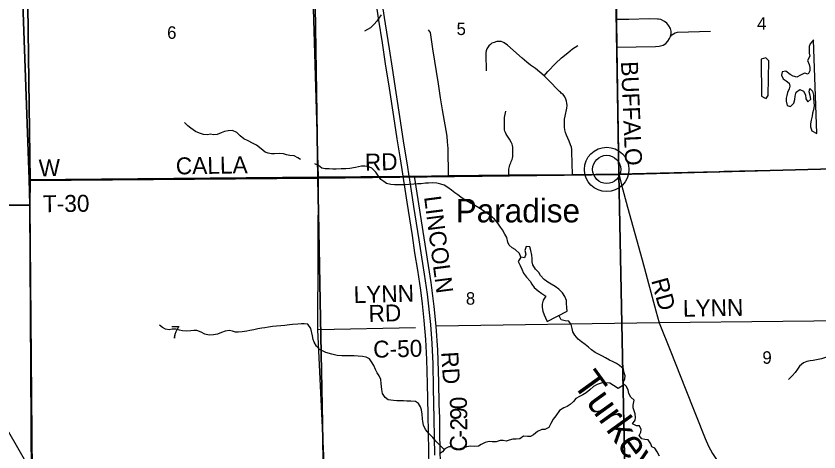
# Model space of a CAD drawing. Extents: x 0 to 36.9, y 0 to 22.
# Drawn here: x 4.166 to 6.858, y 18.601 to 20.063 of the extents above; entities that cross this region are included whole.
import ezdxf

# ---------------------------------------------------------------- set-up
doc = ezdxf.new("R2010")
doc.units = 0
for name, color, linetype in [('GM_X_County_Road', 7, 'Continuous'), ('GM_X_County_Road_Text', 7, 'Continuous'), ('GM_X_Minor_Lake', 7, 'Continuous'), ('GM_X_Minor_River', 7, 'Continuous'), ('GM_X_Minor_River_Text', 7, 'Continuous'), ('GM_X_Rail_Line', 7, 'Continuous'), ('GM_X_Section', 7, 'Continuous'), ('GM_X_Section_Text', 7, 'Continuous'), ('GM_X_State_Route', 7, 'Continuous'), ('GM_X_Township_Road', 7, 'Continuous'), ('GM_X_Township_Road_Text', 7, 'Continuous'), ('GM_X_Unincorporated', 7, 'Continuous'), ('GM_X_Unincorporated_Location', 7, 'Continuous'), ('GM_X_Unincorporated_Text', 7, 'Continuous')]:
    doc.layers.add(name, color=color, linetype=linetype)

msp = doc.modelspace()

# ---------------------------------------------------------------- linework, layer by layer
at = {"layer": 'GM_X_County_Road'}
for p, q in [((5.1803, 19.5234), (5.1498, 20.5289)), ((4.2126, 19.4308), (4.2097, 19.515)), ((5.5055, 19.0174), (5.1771, 19.01))]:
    msp.add_line(p, q, dxfattribs=at)
for points in [[(6.1729, 20.5473), (6.1788, 20.0773), (6.1787, 20.0516), (6.1801, 19.9585), (6.187, 19.5342)], [(5.0673, 17.4931), (5.0594, 17.9986), (5.0622, 18.0085), (5.0708, 18.0163), (5.188, 18.0224), (5.1928, 18.0266), (5.1952, 18.0408), (5.2008, 18.5186), (5.1771, 19.01), (5.1803, 19.5234)], [(5.6045, 18.5243), (5.5945, 18.533), (5.5895, 18.5452), (5.5877, 18.5992), (5.5866, 18.6737), (5.5863, 18.715), (5.5843, 18.7612), (5.5835, 18.8365), (5.5797, 18.9426), (5.5744, 19.0226), (5.5675, 19.0889), (5.5575, 19.1695), (5.5019, 19.5264)], [(6.187, 19.5342), (6.1956, 19.4972), (6.2161, 19.4219), (6.2648, 19.2449), (6.3107, 19.0737), (6.3225, 19.0341)], [(3.21, 19.4177), (3.802, 19.4268), (4.2126, 19.4308)], [(7.1513, 19.0425), (6.3225, 19.0341), (5.5744, 19.0226)], [(6.3225, 19.0341), (6.3608, 18.9363), (6.4096, 18.8146), (6.4758, 18.6464), (6.4875, 18.6201), (6.5008, 18.5958), (6.5286, 18.5528), (6.5955, 18.45), (6.6081, 18.4277), (6.6215, 18.3998), (6.6322, 18.3709), (6.638, 18.3599), (6.6455, 18.3515), (6.6522, 18.3445)]]:
    msp.add_lwpolyline(points, dxfattribs=at)
at = {"layer": 'GM_X_Minor_Lake'}
for points in [[(6.8392, 19.983), (6.8279, 19.9705), (6.8254, 19.961), (6.8252, 19.9485), (6.8254, 19.939), (6.8267, 19.9284), (6.819, 19.9138), (6.8249, 19.901), (6.8277, 19.8908), (6.8271, 19.8794), (6.8216, 19.8679), (6.809, 19.8719), (6.7962, 19.8648), (6.7833, 19.8585), (6.7711, 19.8613), (6.7612, 19.8673), (6.7465, 19.8784), (6.734, 19.8767), (6.7319, 19.8645), (6.7378, 19.8524), (6.7474, 19.8465), (6.7574, 19.8383), (6.7603, 19.8281), (6.7578, 19.8186), (6.7519, 19.8067), (6.7501, 19.7972), (6.7484, 19.7877), (6.7481, 19.7782), (6.7507, 19.763), (6.7625, 19.7598), (6.7734, 19.7706), (6.777, 19.7836), (6.7783, 19.795), (6.7815, 19.8076), (6.7935, 19.8169), (6.8065, 19.8118), (6.8128, 19.7986), (6.8138, 19.7861), (6.82, 19.776), (6.8309, 19.7845), (6.8281, 19.7962), (6.8245, 19.8087), (6.8277, 19.8205), (6.8362, 19.8108), (6.8391, 19.7976), (6.84, 19.7881), (6.8406, 19.7737), (6.8412, 19.763), (6.8399, 19.7486), (6.8366, 19.7371), (6.8345, 19.7272), (6.8313, 19.7139), (6.8296, 19.7021), (6.829, 19.6918), (6.8334, 19.6782), (6.8506, 19.6689)], [(6.8506, 19.6689), (6.8392, 19.983)], [(6.6897, 19.9131), (6.68, 19.9232), (6.6637, 19.9188), (6.6657, 19.7947), (6.675, 19.7884), (6.6807, 19.7869), (6.6874, 19.7965)], [(6.6874, 19.7965), (6.6897, 19.9131)], [(6.0131, 19.0734), (6.0129, 19.0852), (6.0119, 19.0992), (6.011, 19.1087), (6.0062, 19.1223), (5.9984, 19.1343), (5.9853, 19.1474), (5.9734, 19.1555), (5.9595, 19.1637), (5.9484, 19.1707), (5.9365, 19.1792), (5.9241, 19.1931), (5.919, 19.2032), (5.9074, 19.2144), (5.8988, 19.2291), (5.8963, 19.2389), (5.8962, 19.2499), (5.8952, 19.2613), (5.8923, 19.2765), (5.8883, 19.2889), (5.8758, 19.2899), (5.8714, 19.2765), (5.8746, 19.264), (5.8706, 19.2526), (5.8585, 19.2539), (5.8496, 19.2397), (5.8559, 19.2265), (5.8618, 19.2141), (5.8677, 19.2005), (5.877, 19.187), (5.8894, 19.1743), (5.8957, 19.1634), (5.9034, 19.1529), (5.9162, 19.1409), (5.9292, 19.1324), (5.9416, 19.1231), (5.933, 19.1101), (5.9294, 19.0963), (5.9296, 19.0857), (5.9321, 19.0732), (5.9369, 19.0604), (5.9412, 19.0506), (5.9471, 19.0389)], [(5.9471, 19.0389), (6.0131, 19.0734)]]:
    msp.add_lwpolyline(points, dxfattribs=at)
at = {"layer": 'GM_X_Minor_River'}
for points in [[(5.3902, 20.0674), (5.382, 20.0566), (5.375, 20.0462), (5.3665, 20.0358), (5.3538, 20.0238), (5.344, 20.0179), (5.3338, 20.0125)], [(5.1198, 19.5816), (5.1102, 19.5879), (5.0983, 19.5941), (5.0834, 19.5958), (5.0731, 19.5982), (5.0621, 19.6011), (5.048, 19.6024), (5.0328, 19.6009), (5.0226, 19.6008), (5.0112, 19.6028), (5.0016, 19.6068), (4.9877, 19.618), (4.9723, 19.6299), (4.9582, 19.6364), (4.9436, 19.6445), (4.9294, 19.6511), (4.9175, 19.6619), (4.9059, 19.6723), (4.8921, 19.6789), (4.8769, 19.6783), (4.8652, 19.6765), (4.8539, 19.6718), (4.8403, 19.6662), (4.8274, 19.6652), (4.8179, 19.6666), (4.8077, 19.6653), (4.794, 19.6662), (4.7814, 19.6701), (4.768, 19.6763), (4.7518, 19.6867), (4.7418, 19.6945), (4.7306, 19.7057)], [(5.8585, 19.2539), (5.8537, 19.2663), (5.8394, 19.2797), (5.8287, 19.2852), (5.8186, 19.2949), (5.8143, 19.3051), (5.811, 19.3206), (5.8051, 19.3315), (5.7972, 19.3458), (5.7902, 19.3555), (5.7816, 19.3679), (5.7704, 19.3817), (5.7546, 19.3955), (5.743, 19.4025), (5.7304, 19.4114), (5.7169, 19.4199), (5.7039, 19.4276), (5.692, 19.4346), (5.6789, 19.4416), (5.6678, 19.4482), (5.6567, 19.456), (5.647, 19.4631), (5.6374, 19.4705), (5.6259, 19.479), (5.6139, 19.4879), (5.6009, 19.4956), (5.5906, 19.4996), (5.5765, 19.5028), (5.5628, 19.5041), (5.5487, 19.5031), (5.5385, 19.5021), (5.5245, 19.5007), (5.512, 19.5001), (5.4991, 19.4991), (5.4831, 19.4981), (5.4721, 19.4975), (5.4596, 19.4969), (5.4478, 19.4971), (5.4342, 19.4972), (5.4227, 19.4985), (5.4083, 19.5017), (5.3986, 19.5084), (5.389, 19.5146), (5.3785, 19.5289), (5.3719, 19.539), (5.3587, 19.5532), (5.3457, 19.5587), (5.3355, 19.5596), (5.3245, 19.5591), (5.304, 19.5553), (5.2847, 19.5519), (5.2714, 19.5509), (5.2555, 19.5502), (5.2388, 19.5499), (5.2278, 19.5501), (5.216, 19.5503), (5.202, 19.5512), (5.1913, 19.5529), (5.1801, 19.5622), (5.1679, 19.5677)], [(6.3234, 18.5862), (6.3152, 18.6008), (6.3074, 18.6136), (6.2978, 18.6176), (6.2938, 18.6285), (6.2856, 18.6413), (6.2738, 18.643), (6.2635, 18.6451), (6.2553, 18.6563), (6.2601, 18.6666), (6.2618, 18.6765), (6.2563, 18.6886), (6.2464, 18.688), (6.2326, 18.6954), (6.2419, 18.7073), (6.2432, 18.7168), (6.2411, 18.7285), (6.2383, 18.7387), (6.2347, 18.7485), (6.2349, 18.758), (6.238, 18.7744), (6.2272, 18.7848), (6.2202, 18.7973), (6.218, 18.8097), (6.2117, 18.8218), (6.2006, 18.8318), (6.2075, 18.846), (6.2081, 18.8566), (6.2041, 18.8691), (6.2024, 18.8793), (6.1896, 18.8908), (6.1785, 18.8975), (6.1651, 18.9037), (6.1555, 18.9084), (6.1425, 18.9162), (6.1317, 18.9217), (6.1206, 18.9272), (6.108, 18.9349), (6.0956, 18.9438), (6.0852, 18.9524), (6.0737, 18.9613), (6.0614, 18.9698), (6.0506, 18.9791), (6.0397, 18.9922), (6.0323, 19.0042), (6.0302, 19.0151), (6.0266, 19.028), (6.0191, 19.04), (6.007, 19.0402), (5.9936, 19.0445), (5.9862, 19.0594)], [(5.6013, 18.6089), (5.5737, 18.6369), (5.5632, 18.6492), (5.5505, 18.6615), (5.5384, 18.6761), (5.5317, 18.6904), (5.5296, 18.7026), (5.5287, 18.7124), (5.5273, 18.7276), (5.5251, 18.7416), (5.5223, 18.7518), (5.5152, 18.7634), (5.5056, 18.7697), (5.49, 18.7709), (5.476, 18.7714), (5.4646, 18.772), (5.4528, 18.7718), (5.4422, 18.772), (5.4308, 18.7733), (5.414, 18.7757), (5.4032, 18.7831), (5.395, 18.797), (5.3925, 18.8106), (5.3902, 18.8299), (5.3885, 18.8439), (5.3833, 18.856), (5.3763, 18.8661), (5.3712, 18.8778), (5.3656, 18.8906), (5.3578, 18.903), (5.3508, 18.9135), (5.3397, 18.9186), (5.3271, 18.9214), (5.3134, 18.9223), (5.299, 18.9228), (5.2823, 18.9232), (5.2697, 18.923), (5.2583, 18.9232), (5.2424, 18.9248), (5.2248, 18.9283), (5.2046, 18.934), (5.195, 18.9384), (5.1835, 18.9446), (5.1727, 18.9562), (5.1653, 18.9686), (5.162, 18.9784), (5.1596, 18.9902), (5.1546, 19.0151), (5.144, 19.0297), (5.1322, 19.031), (5.1224, 19.0305), (5.1102, 19.0295), (5.0928, 19.0284), (5.0826, 19.0275), (5.0667, 19.0253), (5.0541, 19.024), (5.039, 19.0226), (5.0253, 19.0212), (5.0121, 19.0194), (5, 19.0173), (4.9901, 19.0164), (4.9765, 19.0139), (4.9632, 19.011), (4.9493, 19.0081), (4.9394, 19.006), (4.9235, 19.0038), (4.9106, 19.0028), (4.9011, 19.003), (4.8916, 19.0055), (4.8813, 19.0084), (4.8669, 19.0062), (4.8544, 19.0018), (4.8413, 18.9955), (4.828, 18.9938), (4.8128, 18.9931), (4.7991, 18.9959), (4.7861, 19.0029), (4.7715, 19.0083), (4.7617, 19.0081), (4.7518, 19.0076), (4.7382, 19.0058), (4.7237, 19.0075), (4.7134, 19.0099), (4.702, 19.0124), (4.6894, 19.0125), (4.6796, 19.0109), (4.667, 19.0125), (4.6574, 19.0184), (4.6471, 19.0262)], [(6.9595, 18.9484), (6.9352, 18.9495), (6.9246, 18.947), (6.9137, 18.94), (6.9028, 18.9303), (6.8923, 18.9236), (6.8795, 18.9181), (6.8663, 18.9137), (6.8493, 18.9099), (6.8387, 18.9079), (6.8285, 18.9061), (6.8171, 18.904), (6.8062, 18.9), (6.7931, 18.8888), (6.7857, 18.8788), (6.7783, 18.8677), (6.7682, 18.8561), (6.7555, 18.8441)], [(6.206, 18.827), (6.1842, 18.8133), (6.1688, 18.824), (6.1569, 18.8318), (6.1383, 18.833), (6.1276, 18.8317), (6.1144, 18.8269), (6.1024, 18.8206), (6.0901, 18.8097), (6.077, 18.7992), (6.0664, 18.7926), (6.0555, 18.7867), (6.0428, 18.7796), (6.035, 18.7696), (6.0237, 18.7596), (6.0136, 18.7533), (6.0027, 18.7486), (5.9876, 18.7399), (5.9758, 18.7219), (5.9662, 18.7103), (5.9588, 18.6962), (5.9518, 18.6827), (5.9387, 18.6757), (5.9292, 18.6755), (5.9137, 18.6688), (5.9006, 18.6583), (5.8905, 18.6528), (5.8802, 18.6522), (5.8673, 18.6535), (5.8549, 18.645), (5.8428, 18.644), (5.8314, 18.6434), (5.8189, 18.6398), (5.8087, 18.6369), (5.7985, 18.6386), (5.789, 18.6388), (5.7757, 18.6344), (5.7625, 18.6346), (5.7522, 18.6355), (5.7386, 18.6319), (5.7258, 18.6256), (5.716, 18.6205), (5.7016, 18.6191), (5.6898, 18.62), (5.6758, 18.6175), (5.6622, 18.6119), (5.6478, 18.6101), (5.636, 18.6137), (5.6264, 18.6177), (5.6166, 18.6179), (5.6034, 18.6116), (5.5956, 18.6016), (5.5855, 18.5942)]]:
    msp.add_lwpolyline(points, dxfattribs=at)
at = {"layer": 'GM_X_Rail_Line'}
for points in [[(8.9, 14.5158), (8.9, 20.5927), (8.7004, 20.5894), (8.4791, 20.5781), (8.4706, 20.5777), (8.1451, 20.581), (7.7514, 20.5725), (7.4889, 20.5693), (7.1656, 20.5637), (7.1468, 20.5633), (6.1727, 20.5478), (5.9236, 20.5446), (5.3186, 20.5329), (5.2978, 20.5324), (5.1496, 20.5295), (4.5929, 20.5183), (4.1742, 20.5119), (4.2095, 19.5156), (4.2124, 19.4314), (4.22, 18.531), (4.2174, 18.4382), (4.2214, 17.442), (4.2237, 16.806), (4.2428, 16.065)], [(4.2428, 16.065), (4.2237, 16.806), (4.2214, 17.442), (4.2174, 18.4382), (4.22, 18.531), (4.2124, 19.4314), (4.2095, 19.5156), (4.1742, 20.5119), (3.4355, 20.4995), (3.1942, 20.4953), (2.6054, 20.4898), (2.1, 20.4802), (2.1, 14.4405)]]:
    msp.add_lwpolyline(points, dxfattribs=at)
at = {"layer": 'GM_X_Section'}
for points in [[(7.1483, 20.5676), (7.1591, 19.5574), (6.1867, 19.5319), (6.1696, 20.5537), (6.9427, 20.5639)], [(6.1696, 20.5537), (6.1867, 19.5319), (5.1777, 19.5195), (5.1623, 20.5304), (5.285, 20.533), (5.9343, 20.5451)], [(4.1996, 20.5167), (4.2133, 19.5112), (4.212, 19.4289), (3.2188, 19.419), (3.2025, 20.497), (3.3829, 20.4998), (3.9553, 20.5131)], [(5.1623, 20.5304), (5.1777, 19.5195), (4.2133, 19.5112), (4.1996, 20.5167), (4.6217, 20.5229)], [(7.1591, 19.5574), (7.173, 18.5435), (6.2072, 18.5313), (6.1867, 19.5319)], [(5.1777, 19.5195), (5.197, 18.519), (4.2176, 18.508), (4.212, 19.4289), (4.2133, 19.5112)], [(6.1867, 19.5319), (6.2072, 18.5313), (5.197, 18.519), (5.1777, 19.5195)], [(4.212, 19.4289), (4.2176, 18.508), (4.219, 18.4391), (3.226, 18.4277), (3.2188, 19.419)]]:
    msp.add_lwpolyline(points, close=True, dxfattribs=at)
at = {"layer": 'GM_X_State_Route'}
for points in [[(5.5518, 18.5008), (5.5494, 18.6039), (5.5482, 18.6658), (5.5474, 18.7263), (5.5452, 18.8301), (5.5436, 18.9104), (5.5401, 18.9785), (5.5346, 19.0413), (5.5284, 19.0973), (5.5226, 19.1436), (5.5124, 19.2106), (5.5034, 19.2688), (5.4945, 19.3274), (5.477, 19.4386), (5.4636, 19.5258), (5.4624, 19.5335), (5.4547, 19.5847), (5.444, 19.6519), (5.4325, 19.7268), (5.4178, 19.8212), (5.4047, 19.9033), (5.394, 19.9735), (5.3823, 20.049), (5.3732, 20.1089)], [(5.5698, 18.5896), (5.5687, 18.6515), (5.5678, 18.712), (5.5657, 18.8158), (5.5641, 18.8961), (5.5606, 18.9642), (5.5563, 19.0287), (5.5448, 19.13), (5.5348, 19.1971), (5.5262, 19.2539), (5.5173, 19.3126), (5.4996, 19.4244), (5.4848, 19.5215), (5.484, 19.5261), (5.478, 19.5644), (5.4665, 19.6373), (5.4552, 19.712), (5.4402, 19.8071), (5.4279, 19.8887), (5.4177, 19.9538), (5.4047, 20.0375), (5.3958, 20.0944)], [(4.2202, 18.5304), (4.0532, 18.8191), (4.0295, 18.8744), (3.802, 19.4268)]]:
    msp.add_lwpolyline(points, dxfattribs=at)
at = {"layer": 'GM_X_Township_Road'}
msp.add_line((4.2097, 19.515), (5.1803, 19.5234), dxfattribs=at)
for points in [[(6.3193, 20.0527), (6.3163, 20.0531), (6.2881, 20.0539), (6.2199, 20.0518), (6.1787, 20.0516)], [(6.36, 19.9948), (6.3621, 20.0045), (6.3618, 20.0123), (6.3601, 20.0216), (6.3549, 20.0307), (6.348, 20.0395), (6.3404, 20.0453), (6.3274, 20.0516), (6.3193, 20.0527)], [(5.6156, 19.5281), (5.6141, 19.6192), (5.6127, 19.6413), (5.6108, 19.6606), (5.5955, 19.7488), (5.5893, 19.7892), (5.5819, 19.8355), (5.5637, 19.9538), (5.5551, 20.0079), (5.5485, 20.0176)], [(6.3649, 20.0001), (6.3696, 20.0037), (6.3759, 20.0073), (6.383, 20.0093), (6.4941, 20.0121)], [(6.031, 19.5319), (6.0296, 19.6075), (6.029, 19.6161), (6.0276, 19.6238), (6.0249, 19.6317), (6.0199, 19.6435), (6.0114, 19.6637), (6.0084, 19.6728), (6.0062, 19.682), (6.005, 19.6909), (6.0044, 19.7014), (6.0046, 19.7094), (6.0052, 19.7171), (6.0074, 19.7278), (6.013, 19.754), (6.0135, 19.7628), (6.0126, 19.7713), (6.0114, 19.7773), (6.0096, 19.784), (6.0053, 19.7923), (5.9999, 19.7996), (5.9938, 19.8046), (5.9911, 19.8075), (5.9878, 19.8104), (5.9495, 19.8498), (5.9416, 19.8574), (5.936, 19.8626), (5.9069, 19.8873), (5.8912, 19.8986), (5.8783, 19.9083), (5.8631, 19.9216), (5.8136, 19.9661), (5.8028, 19.974), (5.7979, 19.976), (5.7918, 19.9774), (5.7844, 19.9782), (5.7773, 19.9776), (5.7687, 19.975), (5.7612, 19.9718), (5.7566, 19.9683), (5.7509, 19.9633), (5.7483, 19.9595), (5.7447, 19.9536), (5.7419, 19.9462), (5.7409, 19.9409), (5.7404, 19.9356), (5.7417, 19.8798)], [(6.1801, 19.9585), (6.3102, 19.9607), (6.3224, 19.9621), (6.3353, 19.9651), (6.3449, 19.9717), (6.351, 19.9793), (6.3567, 19.9876), (6.36, 19.9948), (6.3649, 20.0001)], [(5.936, 19.8626), (5.9486, 19.8773), (5.974, 19.9043), (5.9951, 19.9232), (6.0153, 19.9403), (6.032, 19.953), (6.0489, 19.9641)], [(5.8183, 19.5305), (5.818, 19.5501), (5.8187, 19.5543), (5.8198, 19.5582), (5.8219, 19.5637), (5.8245, 19.5703), (5.8264, 19.5752), (5.829, 19.5817), (5.8305, 19.5867), (5.8314, 19.5916), (5.8316, 19.6042), (5.8312, 19.6233), (5.8303, 19.6285), (5.8289, 19.6335), (5.826, 19.6399), (5.8201, 19.6498), (5.8095, 19.6675), (5.8065, 19.6728), (5.8047, 19.6776), (5.8038, 19.6821), (5.8035, 19.6861), (5.803, 19.718), (5.8036, 19.7233), (5.8079, 19.744)], [(6.5233, 19.5422), (6.5386, 19.5426), (6.8533, 19.55), (7.1087, 19.5562)], [(5.1803, 19.5234), (5.4636, 19.5258), (5.4742, 19.5259), (5.484, 19.5261), (5.5019, 19.5264)], [(5.5019, 19.5264), (5.6156, 19.5281), (5.8183, 19.5305), (6.031, 19.5319), (6.187, 19.5342), (6.4185, 19.5394), (6.5233, 19.5422)]]:
    msp.add_lwpolyline(points, dxfattribs=at)
at = {"layer": 'GM_X_Unincorporated'}
for radius in [0.0744, 0.0472]:
    msp.add_circle((6.1461, 19.5488), radius, dxfattribs=at)
at = {"layer": 'GM_X_Unincorporated_Location'}
msp.add_line((6.1461, 19.5488), (6.1461, 19.5488), dxfattribs=at)

# ---------------------------------------------------------------- texts
at = {"layer": 'GM_X_County_Road_Text'}
for s, height, rotation, p in [('BUFFALO', 0.05682, 272.4109, (6.1939, 19.9104)), ('LINCOLN', 0.05682, 277.377, (5.5337, 19.4565)), ('RD', 0.05682, 285.2091, (6.2948, 19.1761)), ('LYNN', 0.05682, 1.488, (5.2983, 19.0999)), ('LYNN', 0.05682, 0.9924, (6.402, 19.0541)), ('RD', 0.05682, 1.4825, (5.3483, 19.0368)), ('C-50', 0.05682, 1.3726, (5.3639, 18.9166)), ('RD', 0.05682, 273.4534, (5.5913, 18.9358)), ('0', 0.0568, 92.0481, (5.6781, 18.7449)), ('9', 0.0568, 90.7044, (5.6786, 18.7085)), ('2', 0.0568, 89.6524, (5.6784, 18.6723)), ('-', 0.0568, 88.9628, (5.6779, 18.6482)), ('C', 0.0568, 88.708, (5.6769, 18.6013))]:
    msp.add_text(s, height=height, rotation=rotation, dxfattribs=at).set_placement(p)
at = {"layer": 'GM_X_Minor_River_Text'}
msp.add_text('Turkey', height=0.09473, rotation=305.8709, dxfattribs=at).set_placement((6.0299, 18.8302))
at = {"layer": 'GM_X_Section_Text'}
for s, p in [('4', (6.6503, 20.0173)), ('6', (4.6724, 19.987)), ('5', (5.6428, 19.9996)), ('8', (5.674, 19.0949)), ('7', (4.6844, 18.9817)), ('9', (6.6682, 18.8966))]:
    msp.add_text(s, height=0.0419, rotation=0, dxfattribs=at).set_placement(p)
at = {"layer": 'GM_X_Township_Road_Text'}
for s, height, rotation, p in [('RD', 0.05682, 1.4807, (5.336, 19.5443)), ('W', 0.0568, 1.4522, (4.2426, 19.5251)), ('CALLA', 0.05682, 0.9941, (4.702, 19.5318)), ('T-30', 0.05682, 0.7069, (4.2561, 19.405))]:
    msp.add_text(s, height=height, rotation=rotation, dxfattribs=at).set_placement(p)
at = {"layer": 'GM_X_Unincorporated_Text'}
msp.add_text('Paradise', height=0.07898, rotation=0, dxfattribs=at).set_placement((5.6399, 19.371))

doc.saveas('drawing.dxf')
